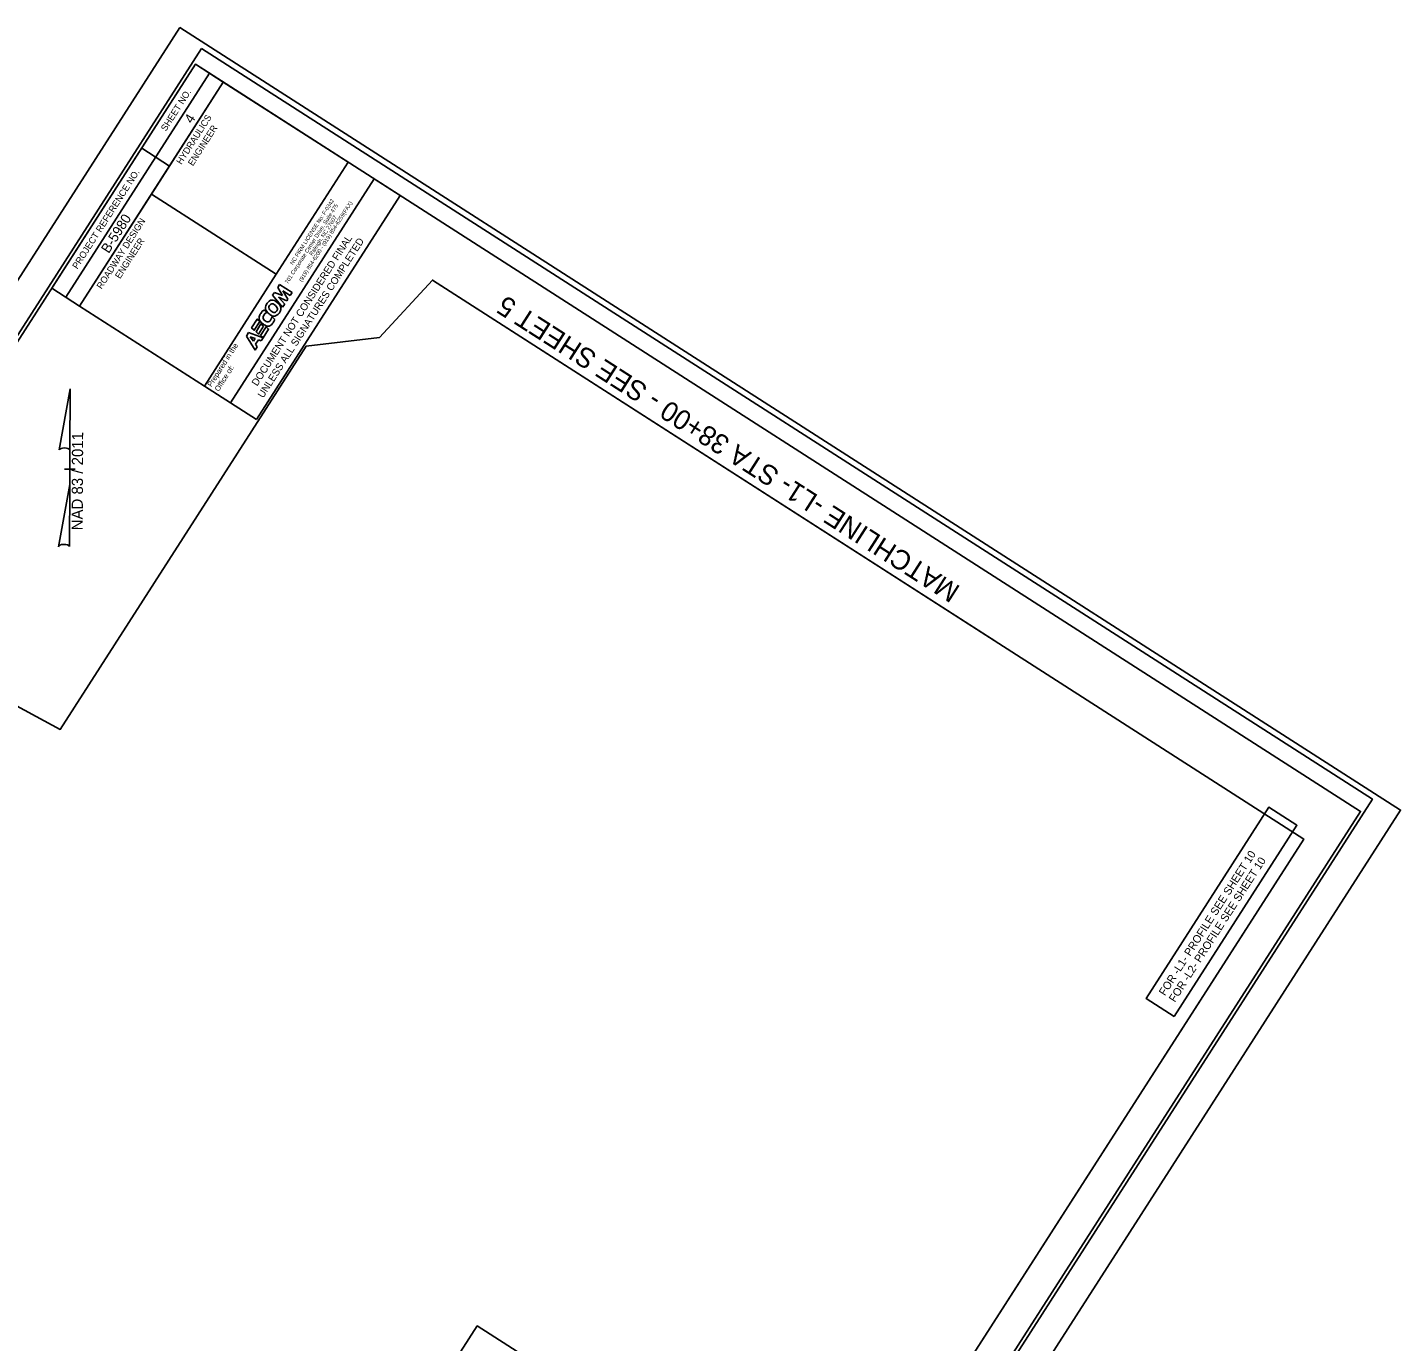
# Model space of a CAD drawing. Extents: x 2346017 to 2347860, y 841201 to 843354.
# Drawn here: x 2346819 to 2347860, y 842357 to 843354 of the extents above; entities that cross this region are included whole.
import ezdxf

# ---------------------------------------------------------------- set-up
doc = ezdxf.new("R2010")
doc.units = 0
for name, color, linetype in [('Default', 7, 'Continuous'), ('Matchline', 7, 'Continuous'), ('Matchline Text', 7, 'Continuous'), ('Old_Level_49', 7, 'Continuous'), ('Prop DSN Text', 7, 'Continuous'), ('Prop North Arrow NAD83 for Plan Sheets CELL', 7, 'Continuous'), ('Prop PFL Text', 7, 'Continuous'), ('Sheet Border Standard 30in CELL', 7, 'Continuous'), ('Sheet Clip Boundary CELL', 7, 'Continuous'), ('Sheet Data Field CELL', 7, 'Continuous'), ('Sheet Plot Border Inside CELL', 7, 'Continuous'), ('Sheet Plot Border Outside CELL', 7, 'Continuous'), ('Sheet Sticker Exception Certification CELL', 7, 'Continuous')]:
    doc.layers.add(name, color=color, linetype=linetype)

# ---------------------------------------------------------------- blocks, each defined once
blk = doc.blocks.new('block 2')
at = {"layer": 'Default'}
for p, q in [((0.10137, 0.08733), (0.10174, 0.08975)), ((0.10782, 0.08733), (0.10137, 0.08733)), ((0.10174, 0.08975), (0.10818, 0.08975)), ((0.10234, 0.09375), (0.10197, 0.09133)), ((0.10197, 0.09133), (0.10929, 0.09133)), ((0.10966, 0.09375), (0.10234, 0.09375)), ((0.10818, 0.08975), (0.10782, 0.08733)), ((0.10929, 0.09133), (0.10966, 0.09375)), ((0.10114, 0.08576), (0.10078, 0.08333)), ((0.10078, 0.08333), (0.1081, 0.08333)), ((0.10846, 0.08576), (0.10114, 0.08576)), ((0.1081, 0.08333), (0.10846, 0.08576))]:
    blk.add_line(p, q, dxfattribs=at)
for points in [[(0.10782, 0.08733), (0.10137, 0.08733), (0.10174, 0.08975), (0.10818, 0.08975), (0.10782, 0.08733)], [(0.10929, 0.09133), (0.10197, 0.09133), (0.10234, 0.09375), (0.10966, 0.09375), (0.10929, 0.09133)], [(0.10846, 0.08576), (0.10114, 0.08576), (0.10078, 0.08333), (0.1081, 0.08333), (0.10846, 0.08576)]]:
    blk.add_lwpolyline(points, dxfattribs=at)

msp = doc.modelspace()

# ---------------------------------------------------------------- linework, layer by layer
at = {"layer": 'Default'}
msp.add_line((2346972.8, 843069.4), (2347081.8, 843239.4), dxfattribs=at)
at = {"layer": 'Matchline'}
msp.add_line((2347125.9, 843162.5), (2347553.3, 842888.4), dxfattribs=at)
at = {"layer": 'Old_Level_49'}
for p, q in [((2347009.9, 843159.2), (2347008.6, 843157)), ((2347019.6, 843153.2), (2347009.9, 843159.2)), ((2347006.1, 843153.2), (2347004.7, 843151)), ((2347004.7, 843151), (2347012.3, 843142)), ((2347012.2, 843150.8), (2347006.1, 843153.2)), ((2347008.6, 843157), (2347012.2, 843150.8)), ((2347013.9, 843144.3), (2347009.3, 843149.5)), ((2347009.3, 843149.5), (2347015.5, 843146.9)), ((2347016.3, 843148.1), (2347012.5, 843154.5)), ((2347012.5, 843154.5), (2347018.1, 843150.9)), ((2347018.1, 843150.9), (2347019.6, 843153.2)), ((2347012.3, 843142), (2347013.9, 843144.3)), ((2347015.5, 843146.9), (2347016.3, 843148.1)), ((2346986.5, 843122.7), (2346984.9, 843120.1)), ((2346984.9, 843120.1), (2346991.5, 843109.5)), ((2346997.5, 843118.8), (2346986.5, 843122.7)), ((2346990.2, 843116.1), (2346987.8, 843119.6)), ((2346987.8, 843119.6), (2346987.8, 843119.6)), ((2346987.8, 843119.6), (2346991.5, 843118.2)), ((2346991.5, 843118.2), (2346990.2, 843116.1)), ((2346996, 843116.5), (2346997.5, 843118.8)), ((2346991.5, 843109.5), (2346993.1, 843111.9)), ((2346991.7, 843113.9), (2346993.9, 843117.3)), ((2346993.1, 843111.9), (2346991.7, 843113.9)), ((2346993.9, 843117.3), (2346996, 843116.5))]:
    msp.add_line(p, q, dxfattribs=at)
for points in [[(2347004.2, 843134.7), (2347004.1, 843133.9), (2347003.6, 843132.9), (2347003.3, 843132.4), (2347002.3, 843130.9), (2347000.6, 843130.6), (2346999.1, 843131.6), (2346997.6, 843132.7), (2346997.2, 843134.7), (2346998.3, 843136.3), (2346998.8, 843137.1), (2346999.5, 843137.6), (2347000.4, 843137.9), (2347000.4, 843137.9), (2346998.4, 843139.8), (2346998.4, 843139.8), (2346997.2, 843139.2), (2346996.5, 843138.6), (2346995.9, 843137.6), (2346994.1, 843134.9), (2346994.9, 843131.1), (2346997.7, 843129.2), (2347000.5, 843127.3), (2347003.6, 843127.9), (2347005.3, 843130.6), (2347005.6, 843131), (2347006.2, 843132.1), (2347006.3, 843132.9), (2347006.3, 843132.9), (2347004.2, 843134.7), (2347004.2, 843134.7)], [(2347008.8, 843136.5), (2347007, 843134.9), (2347004.4, 843135), (2347002.1, 843136.8), (2346999.5, 843138.9), (2346998.8, 843142.6), (2347000.7, 843145)], [(2347000.7, 843145), (2347002.5, 843147.5), (2347005.6, 843147.7), (2347008.1, 843145.7), (2347010.8, 843143.5), (2347011.4, 843139.9), (2347009.6, 843137.4), (2347009.4, 843137.1), (2347009.1, 843136.8), (2347008.8, 843136.5)], [(2347006.9, 843143.2), (2347005.5, 843144.6), (2347003.9, 843144.8), (2347002.9, 843143.8), (2347001.7, 843142.6), (2347002, 843140.7), (2347003.4, 843139.3), (2347004.8, 843137.9), (2347006.5, 843137.7), (2347007.5, 843138.7), (2347008.6, 843139.9), (2347008.4, 843141.8), (2347006.9, 843143.2)]]:
    msp.add_open_spline(points, degree=3, dxfattribs=at)
at = {"layer": 'Prop North Arrow NAD83 for Plan Sheets CELL'}
for p, q in [((2346842.7, 843033.7), (2346851.1, 843080.1)), ((2346851.1, 843080.1), (2346850.9, 843032.3)), ((2346851.1, 843080.1), (2346851.1, 843080.1)), ((2346851.1, 843080.1), (2346851.1, 843080.1)), ((2346850.8, 843007.5), (2346850.9, 843033.7)), ((2346850.9, 843032.3), (2346850.9, 843033.7)), ((2346846.9, 843019.1), (2346846.8, 843019.1)), ((2346846.9, 843019.1), (2346854.9, 843019.1)), ((2346850.4, 843019.1), (2346846.9, 843019.1)), ((2346850.8, 843007.5), (2346842.3, 842960.2)), ((2346850.7, 842960.5), (2346850.8, 843007.5))]:
    msp.add_line(p, q, dxfattribs=at)
for centre, start_param, end_param in [((2346846.8, 843033.3), 0.211319, 2.90315), ((2346846.5, 842960.1), 0.19626, 3.136524)]:
    msp.add_ellipse(centre, major_axis=(4.23, 0), ratio=0.461128, start_param=start_param, end_param=end_param, dxfattribs=at)
at = {"layer": 'Prop PFL Text'}
msp.add_lwpolyline([(2347688.7, 842603.9), (2347781.7, 842748.9), (2347760.4, 842762.6), (2347667.4, 842617.5)], close=True, dxfattribs=at)
at = {"layer": 'Sheet Border Standard 30in CELL'}
for p, q in [((2346847.8, 843149.5), (2346956.8, 843319.6)), ((2346858.3, 843142.8), (2346967.3, 843312.8)), ((2346858.3, 843142.8), (2346967.3, 843312.8)), ((2346905.4, 843262.6), (2346926.4, 843249.1)), ((2346912.8, 843227.8), (2347007.5, 843167.1)), ((2346953, 843082.1), (2346972.8, 843069.4))]:
    msp.add_line(p, q, dxfattribs=at)
for points in [[(2346946.2, 843326.3), (2346128.7, 842051.6), (2347012.6, 841484.8), (2347830.1, 842759.5)], [(2346837.2, 843156.3), (2346946.2, 843326.3), (2346967.3, 843312.8), (2346858.3, 843142.8)], [(2346912.8, 843227.8), (2346967.3, 843312.8), (2347062, 843252.1), (2347007.5, 843167.1)], [(2346858.3, 843142.8), (2346912.8, 843227.8), (2347007.5, 843167.1), (2346953, 843082.1)]]:
    msp.add_lwpolyline(points, close=True, dxfattribs=at)
at = {"layer": 'Sheet Clip Boundary CELL'}
msp.add_line((2347786.9, 842738.5), (2347424.9, 842174), dxfattribs=at)
msp.add_lwpolyline([(2346215, 842139.8), (2346826.4, 841849), (2347159.9, 842369.1), (2347436.3, 842191.8), (2347786.9, 842738.5), (2347125.9, 843162.5), (2347085.8, 843119), (2347030.1, 843112.4), (2346843.6, 842821.7), (2346701.5, 842898.5), (2346607.4, 842751.7)], close=True, dxfattribs=at)
at = {"layer": 'Sheet Plot Border Inside CELL'}
msp.add_lwpolyline([(2346950.9, 843338.3), (2346042.7, 841922.1), (2346930.8, 841352.5), (2347839, 842768.8)], close=True, dxfattribs=at)
at = {"layer": 'Sheet Plot Border Outside CELL'}
msp.add_lwpolyline([(2346934.4, 843354.2), (2346016.7, 841923.2), (2346942.7, 841329.4), (2347860.4, 842760.4)], close=True, dxfattribs=at)
at = {"layer": 'Sheet Sticker Exception Certification CELL'}
for p, q in [((2346972.8, 843069.4), (2347081.8, 843239.4)), ((2347081.8, 843239.4), (2347101.6, 843226.7)), ((2347101.6, 843226.7), (2346992.5, 843056.7)), ((2346992.5, 843056.7), (2346972.8, 843069.4))]:
    msp.add_line(p, q, dxfattribs=at)

# ---------------------------------------------------------------- block references
at = {"layer": 'Old_Level_49', "xscale": 1084.8432715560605, "yscale": 1084.8432715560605, "rotation": 57.32454195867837}
msp.add_blockref('block 2', (2347014.5, 842977.9), dxfattribs=at)

# ---------------------------------------------------------------- texts
at = {"layer": 'Matchline Text'}
msp.add_text('MATCHLINE -L1- STA 38+00 - SEE SHEET 5', height=15, rotation=147.3281, dxfattribs=at).set_placement((2347527.2, 842929.7))
at = {"layer": 'Old_Level_49'}
for s, height, p in [('NC FIRM LICENSE No: F-0342', 3.013, (2347020.1, 843173.8)), ('701 Corporate Center Drive, Suite 475', 3.013, (2347016.3, 843159.4)), ('(919) 854-6200 - (919) 854-6259(FAX)', 3.013, (2347026.9, 843161)), ('Raleigh, NC 27607', 3.013, (2347034.8, 843180.8)), ('Prepared in the ', 4.018, (2346958.3, 843081.2)), ('Office of:', 4.02, (2346963.8, 843077.7))]:
    msp.add_text(s, height=height, rotation=57.3245, dxfattribs=at).set_placement(p)
at = {"layer": 'Prop DSN Text'}
for s, p in [('FOR -L1- PROFILE SEE SHEET 10', (2347681.6, 842619.1)), ('FOR -L2- PROFILE SEE SHEET 10', (2347689.2, 842614.2))]:
    msp.add_text(s, height=6, rotation=57.3281, dxfattribs=at).set_placement(p)
at = {"layer": 'Prop North Arrow NAD83 for Plan Sheets CELL'}
msp.add_text('NAD 83 / 2011', height=8.501, rotation=89.7526, dxfattribs=at).set_placement((2346860.7, 842972.7))
at = {"layer": 'Sheet Border Standard 30in CELL'}
for s, p in [('SHEET NO.', (2346923.8, 843275.1)), ('HYDRAULICS', (2346935.5, 843249.8)), ('ENGINEER', (2346944.3, 843248.7)), ('PROJECT REFERENCE NO.', (2346856.6, 843170.5)), ('ROADWAY DESIGN', (2346875, 843155.3)), ('ENGINEER', (2346889, 843163.1))]:
    msp.add_text(s, height=5, rotation=57.3281, dxfattribs=at).set_placement(p)
at = {"layer": 'Sheet Data Field CELL'}
for s, p in [('4', (2346943.5, 843280.8)), ('B-5980', (2346880.4, 843182.3))]:
    msp.add_text(s, height=7.5, rotation=57.3281, dxfattribs=at).set_placement(p)
at = {"layer": 'Sheet Sticker Exception Certification CELL'}
for s, p in [('DOCUMENT NOT CONSIDERED FINAL', (2346993, 843081.7)), ('UNLESS ALL SIGNATURES COMPLETED', (2346997.6, 843072.6))]:
    msp.add_text(s, height=5.5, rotation=57.3281, dxfattribs=at).set_placement(p)

doc.saveas('drawing.dxf')
